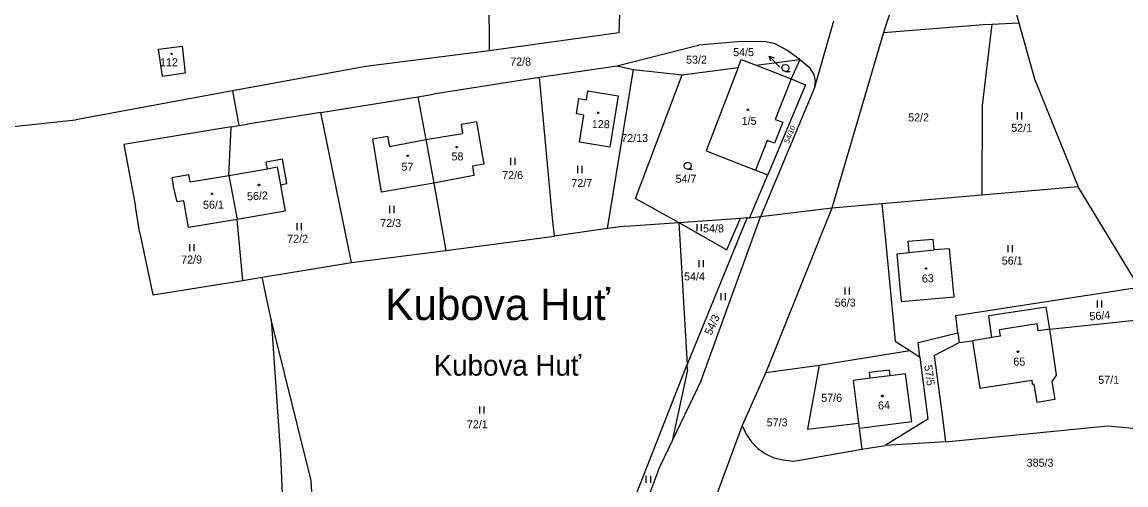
# Model space of a CAD drawing. Extents: x -811039 to -805820, y -1161436 to -1155864.
# Drawn here: x -806771.7 to -806537.2, y -1157981.5 to -1157883.1 of the extents above; entities that cross this region are included whole.
import ezdxf

# ---------------------------------------------------------------- set-up
doc = ezdxf.new("R2010")
doc.units = 0
for name, color, linetype in [('Default', 7, 'Continuous'), ('KN_HRANICE', 7, 'Continuous'), ('KN_KULTURY', 7, 'Continuous'), ('KN_PARCELY', 7, 'Continuous'), ('KN_SLUCKY', 7, 'Continuous')]:
    doc.layers.add(name, color=color, linetype=linetype)

# ---------------------------------------------------------------- blocks, each defined once
blk = doc.blocks.new('304')
at = {"layer": 'Default'}
blk.add_lwpolyline([(0, 0), (-0.38, 0.1), (-0.65, 0.37), (-0.75, 0.74), (-0.65, 1.11), (-0.38, 1.38), (-0.01, 1.48), (0.36, 1.38), (0.63, 1.11), (0.73, 0.73), (0.63, 0.35), (0.36, 0.08), (-0.02, -0.02), (0.98, -0.02)], dxfattribs=at)
blk = doc.blocks.new('306')
at = {"layer": 'Default'}
for p, q in [((-0.5, 1.5), (-0.5, 0)), ((0.5, 0), (0.5, 1.5))]:
    blk.add_line(p, q, dxfattribs=at)
blk = doc.blocks.new('10292')
at = {"layer": 'Default'}
blk.add_line((0, 3), (0, 0), dxfattribs=at)
blk.add_lwpolyline([(-0.5, 2), (0, 3), (0.5, 2)], dxfattribs=at)
blk = doc.blocks.new('402')
at = {"layer": 'Default'}
blk.add_lwpolyline([(0.09, 0.15), (0.18, 0), (0.09, -0.15), (-0.09, -0.15), (-0.18, 0), (-0.09, 0.15), (0.09, 0.15)], dxfattribs=at)

msp = doc.modelspace()

# ---------------------------------------------------------------- linework, layer by layer
at = {"layer": 'KN_HRANICE'}
for p, q in [((-806575.79, -1157845.15), (-806588.75, -1157885.25)), ((-806672.55, -1157877.06), (-806672.48, -1157889.17)), ((-806561.71, -1157877.02), (-806559.95, -1157883.23)), ((-806644.79, -1157881.45), (-806644.96, -1157885.34)), ((-806599.35, -1157882.87), (-806603.42, -1157897.19)), ((-806565.73, -1157883.47), (-806559.95, -1157883.23)), ((-806559.95, -1157883.23), (-806556.68, -1157895.12)), ((-806644.96, -1157885.34), (-806672.48, -1157889.17)), ((-806588.75, -1157885.25), (-806599.71, -1157922.59)), ((-806588.75, -1157885.25), (-806567.58, -1157883.55)), ((-806565.73, -1157883.47), (-806567.75, -1157900.78)), ((-806567.58, -1157883.55), (-806565.73, -1157883.47)), ((-806618.79, -1157887.16), (-806628, -1157887.97)), ((-806613.72, -1157887.23), (-806618.79, -1157887.16)), ((-806611.76, -1157887.71), (-806613.72, -1157887.23)), ((-806609.25, -1157889.03), (-806611.76, -1157887.71)), ((-806742.69, -1157888.8), (-806737.71, -1157888.18)), ((-806741.85, -1157894.61), (-806742.69, -1157888.8)), ((-806737.71, -1157888.18), (-806737.04, -1157893.93)), ((-806672.48, -1157889.17), (-806698.7, -1157892.47)), ((-806645.34, -1157892.38), (-806628, -1157887.97)), ((-806606.48, -1157890.99), (-806609.25, -1157889.03)), ((-806698.7, -1157892.47), (-806727.01, -1157897.69)), ((-806661.79, -1157894.77), (-806645.34, -1157892.38)), ((-806645.34, -1157892.38), (-806641.83, -1157893.15)), ((-806619.6, -1157892.72), (-806618.94, -1157891.01)), ((-806618.94, -1157891.01), (-806615.79, -1157892.22)), ((-806615.79, -1157892.22), (-806606.48, -1157890.99)), ((-806615.79, -1157892.22), (-806608.32, -1157895.09)), ((-806606.48, -1157890.99), (-806608.32, -1157895.09)), ((-806606.48, -1157890.99), (-806604.5, -1157892.65)), ((-806737.04, -1157893.93), (-806741.85, -1157894.61)), ((-806662.28, -1157894.89), (-806684.33, -1157898.4)), ((-806662.28, -1157894.89), (-806661.79, -1157894.77)), ((-806659.05, -1157924.78), (-806661.79, -1157894.77)), ((-806647.34, -1157926.97), (-806641.83, -1157893.15)), ((-806641.83, -1157893.15), (-806631.47, -1157894.29)), ((-806641.39, -1157920.57), (-806631.47, -1157894.29)), ((-806631.47, -1157894.29), (-806619.6, -1157892.72)), ((-806619.6, -1157892.72), (-806626.42, -1157910.41)), ((-806604.5, -1157892.65), (-806603.54, -1157894.19)), ((-806603.54, -1157894.19), (-806603.21, -1157895.65)), ((-806603.42, -1157897.19), (-806614.82, -1157924.5)), ((-806605.26, -1157896.39), (-806613.32, -1157915.55)), ((-806608.32, -1157895.09), (-806605.26, -1157896.39)), ((-806603.21, -1157895.65), (-806603.42, -1157897.19)), ((-806556.68, -1157895.12), (-806547.36, -1157918.12)), ((-806727.01, -1157897.69), (-806760.28, -1157903.83)), ((-806727.01, -1157897.69), (-806725.66, -1157905.03)), ((-806708.25, -1157902.29), (-806687.64, -1157898.94)), ((-806687.64, -1157898.94), (-806684.33, -1157898.4)), ((-806687.64, -1157898.94), (-806685.94, -1157908.02)), ((-806653.94, -1157902.57), (-806653.42, -1157899.34)), ((-806653.42, -1157899.34), (-806651.83, -1157899.59)), ((-806651.83, -1157899.59), (-806651.51, -1157897.68)), ((-806651.51, -1157897.68), (-806645.05, -1157898.75)), ((-806645.05, -1157898.75), (-806646.84, -1157909.65)), ((-806567.75, -1157900.78), (-806567.85, -1157919.87)), ((-806817.49, -1157909.9), (-806760.28, -1157903.83)), ((-806708.25, -1157902.29), (-806723.84, -1157904.73)), ((-806701.71, -1157934.19), (-806708.25, -1157902.29)), ((-806675.16, -1157904.25), (-806678.44, -1157904.81)), ((-806675.16, -1157904.25), (-806673.58, -1157913.28)), ((-806652.36, -1157902.82), (-806653.94, -1157902.57)), ((-806653.31, -1157908.58), (-806652.36, -1157902.82)), ((-806727.26, -1157905.3), (-806750.09, -1157909.08)), ((-806727.76, -1157915.68), (-806727.27, -1157905.51)), ((-806727.27, -1157905.51), (-806727.26, -1157905.3)), ((-806727.26, -1157905.3), (-806725.66, -1157905.03)), ((-806725.66, -1157905.03), (-806723.84, -1157904.73)), ((-806678.44, -1157904.81), (-806678.11, -1157906.76)), ((-806697.21, -1157907.9), (-806694.06, -1157907.31)), ((-806695.33, -1157919.19), (-806697.21, -1157907.9)), ((-806694.06, -1157907.31), (-806693.67, -1157909.51)), ((-806693.67, -1157909.51), (-806685.94, -1157908.02)), ((-806685.94, -1157908.02), (-806678.11, -1157906.76)), ((-806685.94, -1157908.02), (-806684.21, -1157917.28)), ((-806646.84, -1157909.65), (-806653.31, -1157908.58)), ((-806750.09, -1157909.08), (-806747.61, -1157922.27)), ((-806626.42, -1157910.41), (-806615.89, -1157914.54)), ((-806716.35, -1157912.21), (-806719.85, -1157912.87)), ((-806719.55, -1157914.23), (-806719.85, -1157912.87)), ((-806715.42, -1157917.38), (-806716.35, -1157912.21)), ((-806673.58, -1157913.28), (-806676.05, -1157913.68)), ((-806676.05, -1157913.68), (-806675.71, -1157915.67)), ((-806736.25, -1157915.54), (-806739.9, -1157916.2)), ((-806735.97, -1157917.05), (-806736.25, -1157915.54)), ((-806735.97, -1157917.05), (-806727.76, -1157915.68)), ((-806727.76, -1157915.68), (-806719.55, -1157914.23)), ((-806727.76, -1157915.68), (-806726.01, -1157925.05)), ((-806675.71, -1157915.67), (-806684.21, -1157917.28)), ((-806617.21, -1157924.78), (-806613.32, -1157915.55)), ((-806615.89, -1157914.54), (-806613.32, -1157915.55)), ((-806739.9, -1157916.2), (-806739.57, -1157917.74)), ((-806738.73, -1157921.28), (-806739.57, -1157917.74)), ((-806716.78, -1157917.67), (-806715.42, -1157917.38)), ((-806716.78, -1157917.67), (-806715.81, -1157923.24)), ((-806684.21, -1157917.28), (-806695.33, -1157919.19)), ((-806684.21, -1157917.28), (-806681.68, -1157931.59)), ((-806547.36, -1157918.12), (-806567.85, -1157919.87)), ((-806534.45, -1157939.44), (-806547.36, -1157918.12)), ((-806641.39, -1157920.57), (-806632.16, -1157925.65)), ((-806567.85, -1157919.87), (-806589.09, -1157921.68)), ((-806746.65, -1157927.97), (-806747.61, -1157922.27)), ((-806737.35, -1157921.05), (-806738.73, -1157921.28)), ((-806736.37, -1157926.76), (-806737.35, -1157921.05)), ((-806599.71, -1157922.59), (-806614.82, -1157924.5)), ((-806599.71, -1157922.59), (-806613.71, -1157957.59)), ((-806589.09, -1157921.68), (-806599.71, -1157922.59)), ((-806589.09, -1157921.68), (-806588.4, -1157928.68)), ((-806726.01, -1157925.05), (-806736.37, -1157926.76)), ((-806715.81, -1157923.24), (-806726.01, -1157925.05)), ((-806724.78, -1157937.97), (-806726.01, -1157925.05)), ((-806658.62, -1157928.55), (-806659.05, -1157924.78)), ((-806632.16, -1157925.65), (-806619.12, -1157924.72)), ((-806617.7, -1157924.62), (-806630.4, -1157955.86)), ((-806627.45, -1157959.24), (-806614.82, -1157924.5)), ((-806621.97, -1157931.49), (-806619.12, -1157924.72)), ((-806619.12, -1157924.72), (-806617.7, -1157924.62)), ((-806617.7, -1157924.62), (-806617.21, -1157924.78)), ((-806614.82, -1157924.5), (-806617.21, -1157924.78)), ((-806647.34, -1157926.97), (-806658.62, -1157928.55)), ((-806643.46, -1157926.46), (-806647.34, -1157926.97)), ((-806643.46, -1157926.46), (-806632.16, -1157925.65)), ((-806632.16, -1157925.65), (-806621.97, -1157931.49)), ((-806632.16, -1157925.65), (-806630.4, -1157955.86)), ((-806746.65, -1157927.97), (-806743.94, -1157941.04)), ((-806681.68, -1157931.59), (-806658.62, -1157928.55)), ((-806588.4, -1157928.68), (-806586.22, -1157950.91)), ((-806583.48, -1157929.62), (-806578.26, -1157929.19)), ((-806583.24, -1157932.08), (-806583.48, -1157929.62)), ((-806578.26, -1157929.19), (-806578.02, -1157931.49)), ((-806701.71, -1157934.19), (-806681.68, -1157931.59)), ((-806585.86, -1157932.34), (-806583.24, -1157932.08)), ((-806585.86, -1157932.34), (-806584.95, -1157942.48)), ((-806574.69, -1157931.3), (-806578.02, -1157931.49)), ((-806573.75, -1157941.46), (-806574.69, -1157931.3)), ((-806720.71, -1157937.3), (-806701.71, -1157934.19)), ((-806743.94, -1157941.04), (-806724.78, -1157937.97)), ((-806724.78, -1157937.97), (-806720.71, -1157937.3)), ((-806718.75, -1157946.31), (-806720.71, -1157937.3)), ((-806573.34, -1157945.48), (-806534.45, -1157939.44)), ((-806584.95, -1157942.48), (-806573.75, -1157941.46)), ((-806554.2, -1157943.65), (-806566.35, -1157945.51)), ((-806553.43, -1157948.32), (-806554.2, -1157943.65)), ((-806710.29, -1157980.53), (-806718.75, -1157946.31)), ((-806718.75, -1157946.31), (-806716.77, -1157975.04)), ((-806572.94, -1157949.15), (-806573.34, -1157945.48)), ((-806565.72, -1157950.1), (-806566.35, -1157945.51)), ((-806553.43, -1157948.32), (-806530.51, -1157945.95)), ((-806551.96, -1157958.08), (-806553.43, -1157948.32)), ((-806586.22, -1157950.91), (-806583.15, -1157952.92)), ((-806581.39, -1157951.17), (-806572.94, -1157949.15)), ((-806581, -1157954.32), (-806581.39, -1157951.17)), ((-806577.93, -1157953.95), (-806572.62, -1157951.2)), ((-806572.94, -1157949.15), (-806572.62, -1157951.2)), ((-806572.62, -1157951.2), (-806569.82, -1157950.84)), ((-806565.72, -1157950.1), (-806569.82, -1157950.84)), ((-806569.82, -1157950.84), (-806568.28, -1157960.89)), ((-806602.41, -1157955.99), (-806583.15, -1157952.92)), ((-806583.15, -1157952.92), (-806581, -1157954.32)), ((-806650.25, -1158006.25), (-806630.4, -1157955.86)), ((-806630.33, -1157957.02), (-806630.4, -1157955.86)), ((-806581, -1157954.32), (-806579.29, -1157967.51)), ((-806577.93, -1157953.95), (-806576.19, -1157967.14)), ((-806630.33, -1157957.02), (-806633.58, -1157972.08)), ((-806613.71, -1157957.59), (-806618.72, -1157968.82)), ((-806613.71, -1157957.59), (-806602.41, -1157955.99)), ((-806602.41, -1157955.99), (-806604.89, -1157969.58)), ((-806591.71, -1157957.5), (-806587.52, -1157956.99)), ((-806591.53, -1157958.8), (-806591.71, -1157957.5)), ((-806587.52, -1157956.99), (-806587.41, -1157958.28)), ((-806584.02, -1157957.85), (-806587.41, -1157958.28)), ((-806582.74, -1157967.95), (-806584.02, -1157957.85)), ((-806551.96, -1157958.08), (-806552.97, -1157959.48)), ((-806627.45, -1157959.24), (-806633.58, -1157972.08)), ((-806591.53, -1157958.8), (-806595.19, -1157959.28)), ((-806595.19, -1157959.28), (-806594.05, -1157968.36)), ((-806568.28, -1157960.89), (-806557.17, -1157959.19)), ((-806557.05, -1157960.09), (-806557.17, -1157959.19)), ((-806556.71, -1157960.03), (-806557.05, -1157960.09)), ((-806556.1, -1157963.96), (-806556.71, -1157960.03)), ((-806552.97, -1157959.48), (-806552.35, -1157963.33)), ((-806552.35, -1157963.33), (-806556.1, -1157963.96)), ((-806579.29, -1157967.51), (-806588.4, -1157973.11)), ((-806576.19, -1157967.14), (-806575.57, -1157972.28)), ((-806618.72, -1157968.82), (-806624.34, -1157983.98)), ((-806618.72, -1157968.82), (-806617.87, -1157970.67)), ((-806604.89, -1157969.58), (-806594.05, -1157968.36)), ((-806594.05, -1157968.36), (-806593.89, -1157969.41)), ((-806593.89, -1157969.41), (-806582.74, -1157967.95)), ((-806593.89, -1157969.41), (-806593.3, -1157973.89)), ((-806575.57, -1157972.28), (-806541.08, -1157968.88)), ((-806541.08, -1157968.88), (-806531.68, -1157969.79)), ((-806633.58, -1157972.08), (-806636.14, -1157977.4)), ((-806617.87, -1157970.67), (-806616.81, -1157972.26)), ((-806616.81, -1157972.26), (-806615.42, -1157973.71)), ((-806575.57, -1157972.28), (-806588.4, -1157973.11)), ((-806615.42, -1157973.71), (-806613.77, -1157974.87)), ((-806607.8, -1157976.41), (-806593.3, -1157973.89)), ((-806593.3, -1157973.89), (-806588.4, -1157973.11)), ((-806716.77, -1157975.04), (-806715.04, -1158016)), ((-806613.77, -1157974.87), (-806612.01, -1157975.69)), ((-806612.01, -1157975.69), (-806610.02, -1157976.16)), ((-806610.02, -1157976.16), (-806607.8, -1157976.41)), ((-806647.57, -1158007.68), (-806636.14, -1157977.4)), ((-806708.29, -1158014.83), (-806710.29, -1157980.53))]:
    msp.add_line(p, q, dxfattribs=at)
at = {"layer": 'KN_PARCELY'}
msp.add_line((-806610.76, -1157892.62), (-806610.93, -1157892.45), dxfattribs=at)
at = {"layer": 'KN_SLUCKY'}
for p, q in [((-806608.32, -1157895.09), (-806611.7, -1157903.8)), ((-806611.7, -1157903.8), (-806610.13, -1157904.37)), ((-806610.13, -1157904.37), (-806611.9, -1157908.82)), ((-806613.46, -1157908.22), (-806615.89, -1157914.54)), ((-806611.9, -1157908.82), (-806613.46, -1157908.22)), ((-806719.55, -1157914.23), (-806717.48, -1157913.87)), ((-806717.48, -1157913.87), (-806716.78, -1157917.67)), ((-806583.24, -1157932.08), (-806578.02, -1157931.49)), ((-806556.08, -1157947.24), (-806564.13, -1157948.47)), ((-806564.13, -1157948.47), (-806563.94, -1157949.83)), ((-806555.86, -1157948.71), (-806556.08, -1157947.24)), ((-806553.43, -1157948.32), (-806555.86, -1157948.71)), ((-806563.94, -1157949.83), (-806565.72, -1157950.1)), ((-806587.41, -1157958.28), (-806591.53, -1157958.8))]:
    msp.add_line(p, q, dxfattribs=at)

# ---------------------------------------------------------------- block references
at = {"layer": 'KN_KULTURY'}
for name, p in [('402', (-806739.94, -1157889.82)), ('304', (-806609.56, -1157893.54)), ('402', (-806617.53, -1157901.73)), ('402', (-806649.34, -1157902.34)), ('306', (-806559.85, -1157903.74)), ('402', (-806689.79, -1157911.47)), ('402', (-806679.37, -1157909.66)), ('306', (-806667.48, -1157913.44)), ('306', (-806653.24, -1157915.15)), ('304', (-806630.31, -1157914.33)), ('402', (-806721.38, -1157917.7)), ('402', (-806731.32, -1157919.55)), ('306', (-806693.13, -1157923.66)), ('306', (-806712.83, -1157927.31)), ('306', (-806627.85, -1157927.53)), ('306', (-806735.65, -1157931.78)), ('306', (-806561.81, -1157932)), ('306', (-806627.43, -1157935.2)), ('402', (-806579.71, -1157935.44)), ('306', (-806596.46, -1157940.98)), ('306', (-806622.8, -1157942.19)), ('306', (-806542.83, -1157943.76)), ('402', (-806560.15, -1157953.14)), ('402', (-806588.99, -1157962.57)), ('306', (-806674.06, -1157966.3)), ('306', (-806638.67, -1157981.02))]:
    msp.add_blockref(name, p, dxfattribs=at)
at = {"layer": 'KN_PARCELY', "rotation": 44.232341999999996}
msp.add_blockref('10292', (-806610.93, -1157892.45), dxfattribs=at)

# ---------------------------------------------------------------- texts
at = {"layer": 'KN_PARCELY'}
for s, height, p in [('53/2', 1.7, (-806630.65, -1157891.89)), ('54/5', 1.7, (-806620.66, -1157890.3)), ('112', 1.7, (-806742.38, -1157892.45)), ('72/8', 1.7, (-806668.01, -1157892.3)), ('54/5', 0.1, (-806610.96, -1157892.62)), ('128', 1.7, (-806650.67, -1157905.61)), ('1/5', 1.7, (-806618.84, -1157904.91)), ('52/2', 1.7, (-806583.49, -1157904.18)), ('52/1', 1.7, (-806561.58, -1157906.39)), ('72/13', 1.7, (-806644.42, -1157908.56)), ('58', 1.7, (-806680.47, -1157912.47)), ('72/6', 1.7, (-806669.71, -1157916.45)), ('54/7', 1.7, (-806632.88, -1157917.23)), ('72/7', 1.7, (-806655.02, -1157918.12)), ('72/3', 1.7, (-806695.61, -1157926.63)), ('54/8', 1.7, (-806627.05, -1157927.78)), ('72/2', 1.7, (-806715.37, -1157929.97)), ('72/9', 1.7, (-806737.9, -1157934.39)), ('56/1', 1.7, (-806563.6, -1157934.62)), ('54/4', 1.7, (-806631.09, -1157937.98)), ('Kubova Huť', 6.7, (-806694.54, -1157946.41)), ('56/3', 1.7, (-806599.08, -1157943.55)), ('Kubova Huť', 4.4, (-806684.25, -1157958.24)), ('65', 1.7, (-806561.14, -1157956.1)), ('57/1', 1.7, (-806543.11, -1157959.97)), ('57/6', 1.7, (-806601.95, -1157963.79)), ('72/1', 1.7, (-806677.21, -1157969.44)), ('57/3', 1.7, (-806613.53, -1157969.03)), ('385/3', 1.7, (-806558.32, -1157977.6))]:
    msp.add_text(s, height=height, dxfattribs=at).set_placement(p)
for s, height, rotation, p in [('54/10', 1.14, 67.781, (-806608.85, -1157908.98)), ('57', 1.7, 359.13, (-806691.12, -1157914.65)), ('56/2', 1.7, 3.266, (-806723.86, -1157920.98)), ('56/1', 1.7, 0.859, (-806733.24, -1157922.77)), ('63', 1.7, 2.464, (-806580.55, -1157938.47)), ('54/3', 1.7, 65.031, (-806625.3, -1157949.76)), ('56/4', 1.7, 4.297, (-806544.92, -1157946.5)), ('57/5', 1.7, 278.114, (-806580.1, -1157956.09)), ('64', 1.7, 2.807, (-806589.85, -1157965.45))]:
    msp.add_text(s, height=height, rotation=rotation, dxfattribs=at).set_placement(p)

doc.saveas('drawing.dxf')
